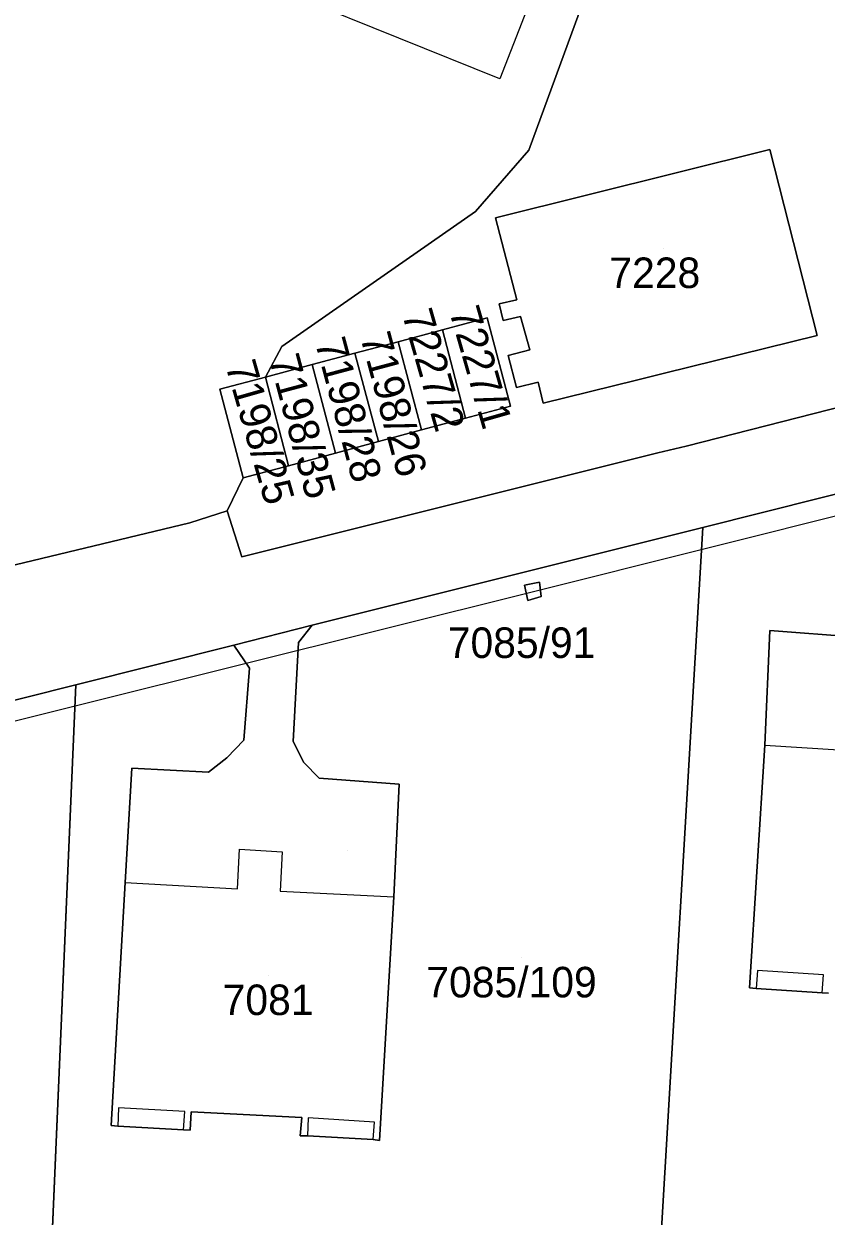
# Model space of a CAD drawing. Extents: x -266199 to -261993, y -1239047 to -1235108.
# Drawn here: x -263685.7 to -263633.2, y -1236679 to -1236600.9 of the extents above; entities that cross this region are included whole.
import ezdxf

# ---------------------------------------------------------------- set-up
doc = ezdxf.new("R2010")
doc.units = 0
for name, color, linetype in [('body_kn', 7, 'Continuous'), ('kladpar_druhypozemkov', 7, 'Continuous'), ('kladpar_hranice', 7, 'Continuous'), ('kladpar_parcelnecisla', 7, 'Continuous'), ('kladpar_plochy', 7, 'Continuous'), ('kladpar_sipky', 7, 'Continuous'), ('linie', 7, 'Continuous'), ('zappar_hrandruhpozemk', 7, 'Continuous')]:
    doc.layers.add(name, color=color, linetype=linetype)

msp = doc.modelspace()

# ---------------------------------------------------------------- linework, layer by layer
at = {"layer": 'body_kn'}
for p, q in [((-263654.54, -1236604.46), (-263654.54, -1236604.46)), ((-263652.65, -1236609.13), (-263652.65, -1236609.13)), ((-263636.86, -1236609.09), (-263636.86, -1236609.09)), ((-263656.13, -1236613.16), (-263656.13, -1236613.16)), ((-263654.82, -1236613.56), (-263654.82, -1236613.56)), ((-263654.58, -1236619.2), (-263654.58, -1236619.2)), ((-263653.44, -1236618.94), (-263653.44, -1236618.94)), ((-263655.38, -1236620.13), (-263655.38, -1236620.13)), ((-263654.33, -1236620.3), (-263654.33, -1236620.3)), ((-263653.19, -1236620.04), (-263653.19, -1236620.04)), ((-263658.31, -1236620.91), (-263658.31, -1236620.91)), ((-263658.31, -1236620.91), (-263658.31, -1236620.91)), ((-263661.21, -1236621.69), (-263661.21, -1236621.69)), ((-263661.21, -1236621.69), (-263661.21, -1236621.69)), ((-263633.77, -1236621.27), (-263633.77, -1236621.27)), ((-263668.82, -1236622.01), (-263668.82, -1236622.01)), ((-263664.04, -1236622.44), (-263664.04, -1236622.44)), ((-263664.04, -1236622.44), (-263664.04, -1236622.44)), ((-263654, -1236622.59), (-263654, -1236622.59)), ((-263652.58, -1236622.22), (-263652.58, -1236622.22)), ((-263666.83, -1236623.18), (-263666.83, -1236623.18)), ((-263666.83, -1236623.18), (-263666.83, -1236623.18)), ((-263669.89, -1236624), (-263669.89, -1236624)), ((-263669.89, -1236624), (-263669.89, -1236624)), ((-263645.6, -1236624.2), (-263645.6, -1236624.2)), ((-263643.75, -1236623.75), (-263643.75, -1236623.75)), ((-263672.89, -1236624.8), (-263672.89, -1236624.8)), ((-263653.45, -1236624.69), (-263653.45, -1236624.69)), ((-263652.03, -1236624.33), (-263652.03, -1236624.33)), ((-263651.71, -1236625.72), (-263651.71, -1236625.72)), ((-263651.71, -1236625.72), (-263651.71, -1236625.72)), ((-263653.84, -1236625.91), (-263653.84, -1236625.91)), ((-263656.79, -1236626.7), (-263656.79, -1236626.7)), ((-263659.68, -1236627.47), (-263659.68, -1236627.47)), ((-263662.5, -1236628.23), (-263662.5, -1236628.23)), ((-263642.35, -1236628.54), (-263642.35, -1236628.54)), ((-263665.3, -1236628.98), (-263665.3, -1236628.98)), ((-263644.19, -1236628.96), (-263644.19, -1236628.96)), ((-263668.39, -1236629.81), (-263668.39, -1236629.81)), ((-263671.36, -1236630.6), (-263671.36, -1236630.6)), ((-263671.36, -1236630.6), (-263671.36, -1236630.6)), ((-263672.4, -1236632.76), (-263672.4, -1236632.76)), ((-263674.85, -1236633.55), (-263674.85, -1236633.55)), ((-263641.26, -1236633.86), (-263641.26, -1236633.86)), ((-263671.45, -1236635.78), (-263671.45, -1236635.78)), ((-263651.95, -1236637.45), (-263651.95, -1236637.45)), ((-263652.93, -1236637.64), (-263652.93, -1236637.64)), ((-263652.33, -1236638.05), (-263652.33, -1236638.05)), ((-263652.71, -1236638.64), (-263652.71, -1236638.64)), ((-263652.71, -1236638.64), (-263652.71, -1236638.64)), ((-263651.83, -1236638.39), (-263651.83, -1236638.39)), ((-263666.84, -1236640.26), (-263666.84, -1236640.26)), ((-263636.86, -1236640.61), (-263636.86, -1236640.61)), ((-263667.73, -1236641.4), (-263667.73, -1236641.4)), ((-263671.97, -1236641.58), (-263671.97, -1236641.58)), ((-263670.94, -1236643.07), (-263670.94, -1236643.07)), ((-263682.31, -1236644.18), (-263682.31, -1236644.18)), ((-263671.3, -1236647.8), (-263671.3, -1236647.8)), ((-263668.08, -1236647.88), (-263668.08, -1236647.88)), ((-263637.19, -1236648.12), (-263637.19, -1236648.12)), ((-263637.19, -1236648.12), (-263637.19, -1236648.12)), ((-263672.43, -1236648.96), (-263672.43, -1236648.96)), ((-263678.64, -1236649.63), (-263678.64, -1236649.63)), ((-263673.62, -1236649.89), (-263673.62, -1236649.89)), ((-263667.38, -1236649.26), (-263667.38, -1236649.26)), ((-263666.37, -1236650.28), (-263666.37, -1236650.28)), ((-263661.13, -1236650.67), (-263661.13, -1236650.67)), ((-263671.59, -1236654.95), (-263671.59, -1236654.95)), ((-263668.79, -1236655.11), (-263668.79, -1236655.11)), ((-263679.08, -1236657.13), (-263679.08, -1236657.13)), ((-263679.08, -1236657.13), (-263679.08, -1236657.13)), ((-263671.72, -1236657.53), (-263671.72, -1236657.53)), ((-263668.94, -1236657.69), (-263668.94, -1236657.69)), ((-263661.49, -1236658.07), (-263661.49, -1236658.07)), ((-263661.49, -1236658.07), (-263661.49, -1236658.07)), ((-263637.67, -1236662.88), (-263637.67, -1236662.88)), ((-263633.34, -1236663.17), (-263633.34, -1236663.17)), ((-263638.2, -1236664.03), (-263638.2, -1236664.03)), ((-263637.76, -1236664.06), (-263637.76, -1236664.06)), ((-263633.44, -1236664.36), (-263633.44, -1236664.36)), ((-263633.44, -1236664.36), (-263633.44, -1236664.36)), ((-263679.51, -1236671.88), (-263679.51, -1236671.88)), ((-263675.17, -1236672.13), (-263675.17, -1236672.13)), ((-263674.75, -1236672.15), (-263674.75, -1236672.15)), ((-263667.51, -1236672.53), (-263667.51, -1236672.53)), ((-263667.09, -1236672.55), (-263667.09, -1236672.55)), ((-263679.99, -1236673.05), (-263679.99, -1236673.05)), ((-263679.57, -1236673.08), (-263679.57, -1236673.08)), ((-263675.27, -1236673.33), (-263675.27, -1236673.33)), ((-263675.27, -1236673.33), (-263675.27, -1236673.33)), ((-263674.83, -1236673.35), (-263674.83, -1236673.35)), ((-263662.76, -1236672.82), (-263662.76, -1236672.82)), ((-263667.63, -1236673.72), (-263667.63, -1236673.72)), ((-263667.14, -1236673.73), (-263667.14, -1236673.73)), ((-263662.84, -1236673.97), (-263662.84, -1236673.97)), ((-263662.84, -1236673.97), (-263662.84, -1236673.97)), ((-263662.42, -1236674.04), (-263662.42, -1236674.04))]:
    msp.add_line(p, q, dxfattribs=at)
at = {"layer": 'kladpar_druhypozemkov'}
for p, q in [((-263643.82, -1236615.57), (-263643.82, -1236615.57)), ((-263655.17, -1236622.99), (-263655.17, -1236622.99)), ((-263657.76, -1236623.95), (-263657.76, -1236623.95)), ((-263661.01, -1236624.67), (-263661.01, -1236624.67)), ((-263663.9, -1236625.38), (-263663.9, -1236625.38)), ((-263667.05, -1236626.24), (-263667.05, -1236626.24)), ((-263669.69, -1236626.95), (-263669.69, -1236626.95)), ((-263652.35, -1236637.83), (-263652.35, -1236637.83)), ((-263664.51, -1236655.05), (-263664.51, -1236655.05)), ((-263653.12, -1236662.05), (-263653.12, -1236662.05)), ((-263669.69, -1236663.21), (-263669.69, -1236663.21))]:
    msp.add_line(p, q, dxfattribs=at)
at = {"layer": 'kladpar_hranice'}
msp.add_line((-263661.49, -1236658.07), (-263662.42, -1236674.04), dxfattribs=at)
for points in [[(-263636.73, -1236565.67), (-263652.65, -1236609.13), (-263656.13, -1236613.16), (-263668.82, -1236622.01), (-263669.89, -1236624), (-263672.89, -1236624.8), (-263671.36, -1236630.6), (-263672.4, -1236632.76), (-263674.85, -1236633.55), (-263818.23, -1236668.04)], [(-263530.98, -1236600.62), (-263601.55, -1236618.12), (-263642.35, -1236628.54), (-263644.19, -1236628.96), (-263671.45, -1236635.78), (-263672.4, -1236632.76), (-263671.36, -1236630.6), (-263668.39, -1236629.81), (-263665.3, -1236628.98), (-263662.5, -1236628.23), (-263659.68, -1236627.47), (-263656.79, -1236626.7), (-263653.84, -1236625.91), (-263655.38, -1236620.13), (-263658.31, -1236620.91), (-263661.21, -1236621.69), (-263664.04, -1236622.44), (-263666.83, -1236623.18), (-263669.89, -1236624), (-263668.82, -1236622.01), (-263656.13, -1236613.16), (-263652.65, -1236609.13), (-263636.73, -1236565.67)], [(-263818.23, -1236668.04), (-263674.85, -1236633.55), (-263672.4, -1236632.76), (-263671.45, -1236635.78), (-263644.19, -1236628.96), (-263642.35, -1236628.54), (-263601.55, -1236618.12), (-263530.98, -1236600.62)], [(-263529.92, -1236600.16), (-263533.65, -1236606.02), (-263533.22, -1236606.88), (-263549.31, -1236610.77), (-263554.3, -1236612.06), (-263562.93, -1236614.23), (-263587.11, -1236620.29), (-263592.24, -1236621.55), (-263602.18, -1236624.03), (-263624.77, -1236629.66), (-263628.67, -1236630.7), (-263629.53, -1236630.92), (-263641.26, -1236633.86), (-263666.84, -1236640.26), (-263671.97, -1236641.58), (-263682.31, -1236644.18), (-263709.57, -1236651.04), (-263714.55, -1236652.26), (-263723.38, -1236654.51), (-263751.32, -1236661.62)], [(-263651.71, -1236625.72), (-263652.03, -1236624.33), (-263653.45, -1236624.69), (-263654, -1236622.59), (-263652.58, -1236622.22), (-263653.19, -1236620.04), (-263654.33, -1236620.3), (-263654.58, -1236619.2), (-263653.44, -1236618.94), (-263654.82, -1236613.56), (-263636.86, -1236609.09), (-263633.77, -1236621.27), (-263643.75, -1236623.75), (-263645.6, -1236624.2), (-263651.71, -1236625.72)], [(-263652.03, -1236624.33), (-263651.71, -1236625.72), (-263645.6, -1236624.2), (-263643.75, -1236623.75), (-263633.77, -1236621.27), (-263636.86, -1236609.09), (-263654.82, -1236613.56), (-263653.44, -1236618.94), (-263654.58, -1236619.2), (-263654.33, -1236620.3), (-263653.19, -1236620.04), (-263652.58, -1236622.22), (-263654, -1236622.59), (-263653.45, -1236624.69), (-263652.03, -1236624.33)], [(-263658.31, -1236620.91), (-263655.38, -1236620.13), (-263653.84, -1236625.91), (-263656.79, -1236626.7), (-263658.31, -1236620.91)], [(-263661.21, -1236621.69), (-263658.31, -1236620.91), (-263656.79, -1236626.7), (-263659.68, -1236627.47), (-263661.21, -1236621.69)], [(-263664.04, -1236622.44), (-263661.21, -1236621.69), (-263659.68, -1236627.47), (-263662.5, -1236628.23), (-263664.04, -1236622.44)], [(-263666.83, -1236623.18), (-263664.04, -1236622.44), (-263662.5, -1236628.23), (-263665.3, -1236628.98), (-263666.83, -1236623.18)], [(-263669.89, -1236624), (-263666.83, -1236623.18), (-263665.3, -1236628.98), (-263668.39, -1236629.81), (-263669.89, -1236624)], [(-263671.36, -1236630.6), (-263672.89, -1236624.8), (-263669.89, -1236624), (-263668.39, -1236629.81), (-263671.36, -1236630.6)], [(-263620.65, -1236665.18), (-263619.56, -1236649.27), (-263619.32, -1236641.79), (-263624.45, -1236641.42), (-263625.41, -1236640.31), (-263626.11, -1236638.94), (-263625.38, -1236631.12), (-263624.77, -1236629.66), (-263602.18, -1236624.03), (-263605.51, -1236676.19), (-263644.25, -1236684.66), (-263641.26, -1236633.86), (-263629.53, -1236630.92), (-263628.67, -1236630.7)], [(-263628.67, -1236630.7), (-263628.32, -1236631.43), (-263629.59, -1236631.47), (-263629.92, -1236634.54), (-263628.69, -1236634.69), (-263629.07, -1236638.75), (-263629.79, -1236639.91), (-263631.16, -1236641.04), (-263636.86, -1236640.61), (-263637.19, -1236648.12), (-263638.2, -1236664.03)], [(-263638.2, -1236664.03), (-263637.19, -1236648.12), (-263636.86, -1236640.61), (-263631.16, -1236641.04), (-263629.79, -1236639.91), (-263629.07, -1236638.75), (-263628.69, -1236634.69), (-263629.92, -1236634.54), (-263629.59, -1236631.47), (-263628.32, -1236631.43)], [(-263662.42, -1236674.04), (-263661.49, -1236658.07), (-263661.13, -1236650.67), (-263666.37, -1236650.28), (-263667.38, -1236649.26), (-263668.08, -1236647.88), (-263667.73, -1236641.4), (-263666.84, -1236640.26), (-263641.26, -1236633.86), (-263644.25, -1236684.66), (-263684.43, -1236693.45)], [(-263652.93, -1236637.64), (-263652.71, -1236638.64), (-263651.83, -1236638.39), (-263651.95, -1236637.45), (-263652.93, -1236637.64)], [(-263652.71, -1236638.64), (-263652.93, -1236637.64), (-263651.95, -1236637.45), (-263651.83, -1236638.39), (-263652.71, -1236638.64)], [(-263679.99, -1236673.05), (-263679.08, -1236657.13), (-263678.64, -1236649.63), (-263673.62, -1236649.89), (-263672.43, -1236648.96), (-263671.3, -1236647.8), (-263670.94, -1236643.07), (-263671.97, -1236641.58), (-263666.84, -1236640.26), (-263667.73, -1236641.4), (-263668.08, -1236647.88), (-263667.38, -1236649.26), (-263666.37, -1236650.28), (-263661.13, -1236650.67), (-263661.49, -1236658.07)], [(-263684.43, -1236693.45), (-263682.31, -1236644.18), (-263671.97, -1236641.58), (-263670.94, -1236643.07), (-263671.3, -1236647.8), (-263672.43, -1236648.96), (-263673.62, -1236649.89), (-263678.64, -1236649.63), (-263679.08, -1236657.13), (-263679.99, -1236673.05)], [(-263704, -1236683.54), (-263703.17, -1236667.45), (-263702.85, -1236660.16), (-263708.33, -1236659.83), (-263709.28, -1236659.17), (-263710.16, -1236658.12), (-263710.1, -1236655.81), (-263710.22, -1236652.34), (-263709.57, -1236651.04), (-263682.31, -1236644.18), (-263684.43, -1236693.45), (-263719.02, -1236701.01)], [(-263638.2, -1236664.03), (-263637.76, -1236664.06), (-263633.44, -1236664.36), (-263633.01, -1236664.38)], [(-263633.01, -1236664.38), (-263633.44, -1236664.36), (-263637.76, -1236664.06), (-263638.2, -1236664.03)], [(-263674.83, -1236673.35), (-263674.75, -1236672.15), (-263667.51, -1236672.53), (-263667.63, -1236673.72)], [(-263667.63, -1236673.72), (-263667.51, -1236672.53), (-263674.75, -1236672.15), (-263674.83, -1236673.35)], [(-263679.99, -1236673.05), (-263679.57, -1236673.08), (-263675.27, -1236673.33), (-263674.83, -1236673.35)], [(-263674.83, -1236673.35), (-263675.27, -1236673.33), (-263679.57, -1236673.08), (-263679.99, -1236673.05)], [(-263667.63, -1236673.72), (-263667.14, -1236673.73), (-263662.84, -1236673.97), (-263662.42, -1236674.04)], [(-263662.42, -1236674.04), (-263662.84, -1236673.97), (-263667.14, -1236673.73), (-263667.63, -1236673.72)]]:
    msp.add_lwpolyline(points, dxfattribs=at)
at = {"layer": 'kladpar_plochy'}
for p, q in [((-263652.65, -1236609.13), (-263636.73, -1236565.67)), ((-263656.13, -1236613.16), (-263652.65, -1236609.13)), ((-263636.86, -1236609.09), (-263654.82, -1236613.56)), ((-263633.77, -1236621.27), (-263636.86, -1236609.09)), ((-263668.82, -1236622.01), (-263656.13, -1236613.16)), ((-263654.82, -1236613.56), (-263653.44, -1236618.94)), ((-263601.55, -1236618.12), (-263642.35, -1236628.54)), ((-263653.44, -1236618.94), (-263654.58, -1236619.2)), ((-263654.58, -1236619.2), (-263654.33, -1236620.3)), ((-263655.38, -1236620.13), (-263658.31, -1236620.91)), ((-263653.84, -1236625.91), (-263655.38, -1236620.13)), ((-263654.33, -1236620.3), (-263653.19, -1236620.04)), ((-263653.19, -1236620.04), (-263652.58, -1236622.22)), ((-263658.31, -1236620.91), (-263661.21, -1236621.69)), ((-263661.21, -1236621.69), (-263664.04, -1236622.44)), ((-263643.75, -1236623.75), (-263633.77, -1236621.27)), ((-263669.89, -1236624), (-263668.82, -1236622.01)), ((-263664.04, -1236622.44), (-263666.83, -1236623.18)), ((-263652.58, -1236622.22), (-263654, -1236622.59)), ((-263654, -1236622.59), (-263653.45, -1236624.69)), ((-263666.83, -1236623.18), (-263669.89, -1236624)), ((-263651.71, -1236625.72), (-263645.6, -1236624.2)), ((-263645.6, -1236624.2), (-263643.75, -1236623.75)), ((-263653.45, -1236624.69), (-263652.03, -1236624.33)), ((-263652.03, -1236624.33), (-263651.71, -1236625.72)), ((-263656.79, -1236626.7), (-263653.84, -1236625.91)), ((-263659.68, -1236627.47), (-263656.79, -1236626.7)), ((-263662.5, -1236628.23), (-263659.68, -1236627.47)), ((-263665.3, -1236628.98), (-263662.5, -1236628.23)), ((-263642.35, -1236628.54), (-263644.19, -1236628.96)), ((-263644.19, -1236628.96), (-263671.45, -1236635.78)), ((-263668.39, -1236629.81), (-263665.3, -1236628.98)), ((-263671.36, -1236630.6), (-263668.39, -1236629.81)), ((-263672.4, -1236632.76), (-263671.36, -1236630.6)), ((-263671.45, -1236635.78), (-263672.4, -1236632.76)), ((-263666.84, -1236640.26), (-263641.26, -1236633.86)), ((-263641.26, -1236633.86), (-263644.25, -1236684.66)), ((-263651.95, -1236637.45), (-263652.93, -1236637.64)), ((-263651.83, -1236638.39), (-263651.95, -1236637.45)), ((-263652.93, -1236637.64), (-263652.71, -1236638.64)), ((-263652.71, -1236638.64), (-263651.83, -1236638.39)), ((-263667.73, -1236641.4), (-263666.84, -1236640.26)), ((-263668.08, -1236647.88), (-263667.73, -1236641.4)), ((-263682.31, -1236644.18), (-263671.97, -1236641.58)), ((-263671.97, -1236641.58), (-263670.94, -1236643.07)), ((-263670.94, -1236643.07), (-263671.3, -1236647.8)), ((-263684.43, -1236693.45), (-263682.31, -1236644.18)), ((-263671.3, -1236647.8), (-263672.43, -1236648.96)), ((-263667.38, -1236649.26), (-263668.08, -1236647.88)), ((-263672.43, -1236648.96), (-263673.62, -1236649.89)), ((-263678.64, -1236649.63), (-263679.08, -1236657.13)), ((-263673.62, -1236649.89), (-263678.64, -1236649.63)), ((-263666.37, -1236650.28), (-263667.38, -1236649.26)), ((-263661.13, -1236650.67), (-263666.37, -1236650.28)), ((-263661.49, -1236658.07), (-263661.13, -1236650.67)), ((-263679.08, -1236657.13), (-263679.99, -1236673.05)), ((-263662.42, -1236674.04), (-263661.49, -1236658.07)), ((-263674.83, -1236673.35), (-263674.75, -1236672.15)), ((-263674.75, -1236672.15), (-263667.51, -1236672.53)), ((-263667.51, -1236672.53), (-263667.63, -1236673.72)), ((-263679.99, -1236673.05), (-263679.57, -1236673.08)), ((-263679.57, -1236673.08), (-263675.27, -1236673.33)), ((-263675.27, -1236673.33), (-263674.83, -1236673.35)), ((-263667.63, -1236673.72), (-263667.14, -1236673.73)), ((-263667.14, -1236673.73), (-263662.84, -1236673.97)), ((-263662.84, -1236673.97), (-263662.42, -1236674.04))]:
    msp.add_line(p, q, dxfattribs=at)
for points in [[(-263636.73, -1236565.67), (-263652.65, -1236609.13), (-263656.13, -1236613.16), (-263668.82, -1236622.01), (-263669.89, -1236624), (-263672.89, -1236624.8), (-263671.36, -1236630.6), (-263672.4, -1236632.76), (-263674.85, -1236633.55), (-263818.23, -1236668.04)], [(-263818.23, -1236668.04), (-263674.85, -1236633.55), (-263672.4, -1236632.76), (-263671.45, -1236635.78), (-263644.19, -1236628.96), (-263642.35, -1236628.54), (-263601.55, -1236618.12), (-263530.98, -1236600.62)], [(-263529.92, -1236600.16), (-263533.65, -1236606.02), (-263533.22, -1236606.88), (-263549.31, -1236610.77), (-263554.3, -1236612.06), (-263562.93, -1236614.23), (-263587.11, -1236620.29), (-263592.24, -1236621.55), (-263602.18, -1236624.03), (-263624.77, -1236629.66), (-263628.67, -1236630.7), (-263629.53, -1236630.92), (-263641.26, -1236633.86), (-263666.84, -1236640.26), (-263671.97, -1236641.58), (-263682.31, -1236644.18), (-263709.57, -1236651.04), (-263714.55, -1236652.26), (-263723.38, -1236654.51), (-263751.32, -1236661.62)], [(-263644.25, -1236684.66), (-263641.26, -1236633.86), (-263629.53, -1236630.92)], [(-263631.16, -1236641.04), (-263636.86, -1236640.61), (-263637.19, -1236648.12), (-263638.2, -1236664.03), (-263637.76, -1236664.06), (-263633.44, -1236664.36), (-263633.01, -1236664.38)], [(-263633.01, -1236664.38), (-263633.44, -1236664.36), (-263637.76, -1236664.06), (-263638.2, -1236664.03), (-263637.19, -1236648.12), (-263636.86, -1236640.61), (-263631.16, -1236641.04)], [(-263704, -1236683.54), (-263703.17, -1236667.45), (-263702.85, -1236660.16), (-263708.33, -1236659.83), (-263709.28, -1236659.17), (-263710.16, -1236658.12), (-263710.1, -1236655.81), (-263710.22, -1236652.34), (-263709.57, -1236651.04), (-263682.31, -1236644.18), (-263684.43, -1236693.45)]]:
    msp.add_lwpolyline(points, dxfattribs=at)
for points in [[(-263651.71, -1236625.72), (-263652.03, -1236624.33), (-263653.45, -1236624.69), (-263654, -1236622.59), (-263652.58, -1236622.22), (-263653.19, -1236620.04), (-263654.33, -1236620.3), (-263654.58, -1236619.2), (-263653.44, -1236618.94), (-263654.82, -1236613.56), (-263636.86, -1236609.09), (-263633.77, -1236621.27), (-263643.75, -1236623.75), (-263645.6, -1236624.2)], [(-263658.31, -1236620.91), (-263655.38, -1236620.13), (-263653.84, -1236625.91), (-263656.79, -1236626.7)], [(-263661.21, -1236621.69), (-263658.31, -1236620.91), (-263656.79, -1236626.7), (-263659.68, -1236627.47)], [(-263664.04, -1236622.44), (-263661.21, -1236621.69), (-263659.68, -1236627.47), (-263662.5, -1236628.23)], [(-263666.83, -1236623.18), (-263664.04, -1236622.44), (-263662.5, -1236628.23), (-263665.3, -1236628.98)], [(-263669.89, -1236624), (-263666.83, -1236623.18), (-263665.3, -1236628.98), (-263668.39, -1236629.81)], [(-263671.36, -1236630.6), (-263672.89, -1236624.8), (-263669.89, -1236624), (-263668.39, -1236629.81)], [(-263652.71, -1236638.64), (-263652.93, -1236637.64), (-263651.95, -1236637.45), (-263651.83, -1236638.39)], [(-263661.49, -1236658.07), (-263662.42, -1236674.04), (-263662.84, -1236673.97), (-263667.14, -1236673.73), (-263667.63, -1236673.72), (-263667.51, -1236672.53), (-263674.75, -1236672.15), (-263674.83, -1236673.35), (-263675.27, -1236673.33), (-263679.57, -1236673.08), (-263679.99, -1236673.05), (-263679.08, -1236657.13), (-263678.64, -1236649.63), (-263673.62, -1236649.89), (-263672.43, -1236648.96), (-263671.3, -1236647.8), (-263670.94, -1236643.07), (-263671.97, -1236641.58), (-263666.84, -1236640.26), (-263667.73, -1236641.4), (-263668.08, -1236647.88), (-263667.38, -1236649.26), (-263666.37, -1236650.28), (-263661.13, -1236650.67)]]:
    msp.add_lwpolyline(points, close=True, dxfattribs=at)
at = {"layer": 'kladpar_sipky'}
msp.add_line((-263652.71, -1236638), (-263652.71, -1236638), dxfattribs=at)
at = {"layer": 'linie'}
msp.add_lwpolyline([(-263908.36, -1236702.07), (-263845.29, -1236686.31), (-263749.77, -1236662.37), (-263652.33, -1236638.05), (-263553.25, -1236613.22), (-263536.97, -1236609.13), (-263532.95, -1236608.14)], dxfattribs=at)
at = {"layer": 'zappar_hrandruhpozemk'}
for p, q in [((-263671.59, -1236654.95), (-263668.79, -1236655.11)), ((-263637.67, -1236662.88), (-263637.76, -1236664.06)), ((-263633.34, -1236663.17), (-263637.67, -1236662.88)), ((-263633.44, -1236664.36), (-263633.34, -1236663.17)), ((-263679.51, -1236671.88), (-263679.57, -1236673.08)), ((-263675.17, -1236672.13), (-263679.51, -1236671.88)), ((-263675.27, -1236673.33), (-263675.17, -1236672.13)), ((-263667.09, -1236672.55), (-263667.14, -1236673.73)), ((-263662.76, -1236672.82), (-263667.09, -1236672.55)), ((-263662.84, -1236673.97), (-263662.76, -1236672.82))]:
    msp.add_line(p, q, dxfattribs=at)
for points in [[(-263659.2, -1236557.44), (-263639.69, -1236566.39), (-263654.54, -1236604.46), (-263674.38, -1236596.44)], [(-263637.19, -1236648.12), (-263629.92, -1236648.59), (-263629.68, -1236645.63)], [(-263679.08, -1236657.13), (-263671.72, -1236657.53), (-263671.59, -1236654.95)], [(-263668.79, -1236655.11), (-263668.94, -1236657.69), (-263661.49, -1236658.07)]]:
    msp.add_lwpolyline(points, dxfattribs=at)

# ---------------------------------------------------------------- texts
at = {"layer": 'kladpar_parcelnecisla'}
for s, p in [('7228', (-263647.37, -1236618.17)), ('7085/91', (-263657.952, -1236642.41)), ('7085/109', (-263659.355, -1236664.65)), ('7081', (-263672.696, -1236665.81))]:
    msp.add_text(s, height=2, dxfattribs=at).set_placement(p)
for s, rotation, p in [('7227/2', 286, (-263660.964, -1236619.865)), ('7227/1', 286, (-263657.877, -1236619.681)), ('7198/26', 285, (-263663.703, -1236621.358)), ('7198/28', 285, (-263666.66, -1236621.715)), ('7198/35', 285, (-263669.682, -1236622.799)), ('7198/25', 286, (-263672.533, -1236623.227))]:
    msp.add_text(s, height=2, rotation=rotation, dxfattribs=at).set_placement(p)

doc.saveas('drawing.dxf')
